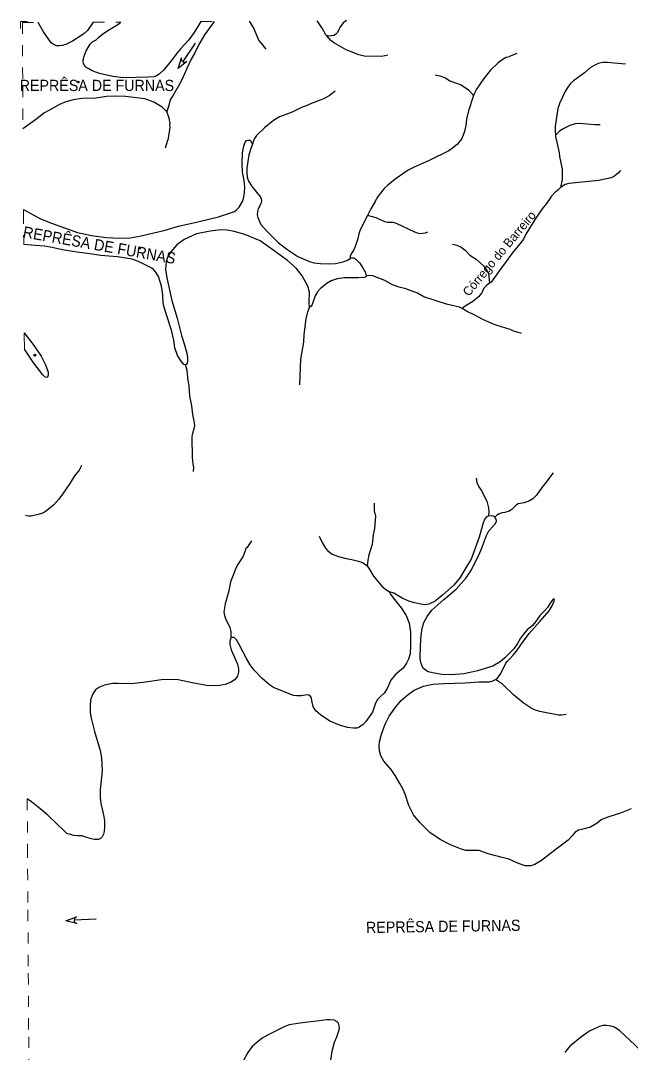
# Model space of a CAD drawing. Extents: x 396 to 422.2, y 7649.8 to 7677.6.
# Drawn here: x 396.05 to 401.48, y 7668.32 to 7677.52 of the extents above; entities that cross this region are included whole.
import ezdxf
from ezdxf.enums import TextEntityAlignment as Align

# ---------------------------------------------------------------- set-up
doc = ezdxf.new("R2010")
doc.units = 0
doc.header["$LTSCALE"] = 0.032
doc.header["$PDMODE"] = 32
doc.header["$PDSIZE"] = 0.016
doc.linetypes.add('SHORT_DASHED', pattern=[2.7, 1.5, -1.2])
for name, color, linetype, lineweight in [('10', 7, 'Continuous', 25), ('2', 7, 'Continuous', 25), ('62', 7, 'SHORT_DASHED', 13), ('63', 7, 'Continuous', 13), ('7', 7, 'Continuous', 25)]:
    doc.layers.add(name, color=color, linetype=linetype, lineweight=lineweight)
doc.layers.add('61', color=7, linetype='Continuous')

msp = doc.modelspace()

# ---------------------------------------------------------------- linework, layer by layer
at = {"layer": '10'}
for p, q in [((397.6028, 7677.3153), (397.4928, 7677.1503)), ((396.7224, 7669.5094), (396.5244, 7669.4992))]:
    msp.add_line(p, q, dxfattribs=at)
for points in [[(397.4808, 7677.1848), (397.4796, 7677.1763), (397.4798, 7677.1704), (397.4829, 7677.1614), (397.4899, 7677.1524), (397.4928, 7677.1503), (397.5004, 7677.1467), (397.5078, 7677.1454), (397.5153, 7677.1454), (397.5223, 7677.1478), (397.5297, 7677.1523), (397.4513, 7677.0881)], [(396.5448, 7669.5294), (396.5373, 7669.5253), (396.5327, 7669.5217), (396.5273, 7669.5138), (396.5243, 7669.5028), (396.5244, 7669.4992), (396.526, 7669.491), (396.5293, 7669.4843), (396.5337, 7669.4783), (396.5399, 7669.4741), (396.5479, 7669.4708), (396.4497, 7669.4954)]]:
    msp.add_lwpolyline(points, close=True, dxfattribs=at)
at = {"layer": '2'}
for points in [[(396.6949, 7677.5016), (396.643, 7677.4274), (396.6152, 7677.4006), (396.5846, 7677.381), (396.5109, 7677.3324), (396.4508, 7677.3034), (396.4174, 7677.2941), (396.3912, 7677.2919), (396.371, 7677.2919), (396.3475, 7677.299), (396.3191, 7677.3182), (396.2508, 7677.4148), (396.2044, 7677.4986)], [(397.6539, 7677.5076), (397.5957, 7677.4088), (397.5477, 7677.3455), (397.4761, 7677.2679), (397.4461, 7677.2329), (397.3789, 7677.1428), (397.3237, 7677.0762), (397.2816, 7677.0379), (397.2581, 7677.0232), (397.2341, 7677.0155), (397.1855, 7677.0106), (397.0746, 7677.009), (396.961, 7677.0057), (396.8697, 7677.0172), (396.7518, 7677.0445), (396.6862, 7677.068), (396.6556, 7677.0849), (396.6294, 7677.1013), (396.6196, 7677.1128), (396.6075, 7677.1324), (396.6043, 7677.145), (396.6043, 7677.1663), (396.6135, 7677.198), (396.6332, 7677.246), (396.6676, 7677.3056), (396.6818, 7677.3214), (396.6917, 7677.3302), (396.7212, 7677.3455), (396.7485, 7677.37), (396.7889, 7677.4039), (396.8386, 7677.4356), (396.9134, 7677.4804), (396.9419, 7677.5032)], [(397.7727, 7677.5083), (397.6875, 7677.3883), (397.6334, 7677.2968), (397.6006, 7677.228), (397.5673, 7677.1723), (397.5296, 7677.0893), (397.4865, 7676.9937), (397.4635, 7676.9494), (397.4073, 7676.8527), (397.3849, 7676.8161), (397.363, 7676.7408), (397.3495, 7676.7065)], [(397.3495, 7676.7065), (397.3379, 7676.7151), (397.3089, 7676.7446), (397.2346, 7676.7888), (397.1533, 7676.82), (397.1052, 7676.8249), (396.9812, 7676.8385), (396.9025, 7676.8435), (396.8129, 7676.8385), (396.7173, 7676.8254), (396.5966, 7676.8205), (396.5169, 7676.8112), (396.4502, 7676.7932), (396.3929, 7676.7675), (396.3, 7676.7151), (396.2541, 7676.6905), (396.1918, 7676.6397), (396.0688, 7676.5507)], [(396.0733, 7675.8334), (396.2252, 7675.7485), (396.3234, 7675.7096), (396.5536, 7675.6277), (396.6805, 7675.6001), (396.8104, 7675.5827), (396.9281, 7675.5776), (397.0243, 7675.5796), (397.1215, 7675.597), (397.3374, 7675.6482), (397.455, 7675.684), (397.6259, 7675.7239), (397.8121, 7675.7679), (397.9185, 7675.8027), (397.9533, 7675.816), (397.9728, 7675.8303), (397.9963, 7675.8528), (398.026, 7675.905), (398.0372, 7675.9439), (398.0434, 7675.9848), (398.0464, 7676.0319), (398.0393, 7676.0923), (398.026, 7676.1659), (398.0208, 7676.2386), (398.026, 7676.3378), (398.0362, 7676.3961), (398.0485, 7676.434), (398.0597, 7676.4463), (398.072, 7676.4504), (398.0894, 7676.4493), (398.0996, 7676.4412), (398.1129, 7676.4162)], [(398.1129, 7676.4162), (398.1037, 7676.3839), (398.0812, 7676.3204), (398.0638, 7676.2007), (398.0638, 7676.1588), (398.0669, 7676.1209), (398.0792, 7676.0841), (398.1099, 7676.035), (398.1774, 7675.9531), (398.1917, 7675.9306), (398.1948, 7675.9101), (398.1886, 7675.8825), (398.1651, 7675.8395), (398.158, 7675.816), (398.1559, 7675.7843), (398.161, 7675.7618), (398.1897, 7675.7004), (398.248, 7675.6329), (398.2869, 7675.595), (398.3452, 7675.5357), (398.4301, 7675.4722), (398.5171, 7675.4149), (398.6225, 7675.3699), (398.6614, 7675.3576), (398.7207, 7675.3505), (398.7923, 7675.3484), (398.8547, 7675.3505), (398.9212, 7675.3668), (398.9622, 7675.3812), (398.9861, 7675.3948)], [(398.6234, 7674.9588), (398.6194, 7675.0067), (398.6214, 7675.0957), (398.6071, 7675.1499), (398.557, 7675.241), (398.5038, 7675.3095), (398.425, 7675.3781), (398.2756, 7675.4876), (398.1815, 7675.553), (398.0464, 7675.6103), (397.9523, 7675.638), (397.8899, 7675.6482), (397.8326, 7675.6513), (397.7364, 7675.64), (397.6157, 7675.6155), (397.5062, 7675.5663), (397.4397, 7675.5183), (397.3875, 7675.4558), (397.3599, 7675.4139), (397.3445, 7675.3679), (397.3394, 7675.2993), (397.3496, 7675.2236), (397.3967, 7675.021), (397.4438, 7674.8634), (397.4827, 7674.7089), (397.5093, 7674.626), (397.5318, 7674.5391), (397.5338, 7674.5053), (397.5348, 7674.4818), (397.5307, 7674.4634), (397.5246, 7674.4531), (397.5165, 7674.4491)], [(397.5165, 7674.4491), (397.5021, 7674.4521), (397.4775, 7674.4818), (397.4468, 7674.5309), (397.4223, 7674.5994), (397.4121, 7674.667), (397.3916, 7674.756), (397.3507, 7674.8859), (397.323, 7674.9698), (397.319, 7675.0016), (397.3159, 7675.0711), (397.3046, 7675.1489), (397.276, 7675.2348), (397.2535, 7675.2747), (397.233, 7675.2973), (397.2166, 7675.3106), (397.1808, 7675.3269), (397.145, 7675.3443), (397.0979, 7675.3689), (397.0427, 7675.3893), (396.9097, 7675.4118), (396.7593, 7675.4241), (396.6672, 7675.4384), (396.5495, 7675.4538), (396.4216, 7675.4722), (396.3275, 7675.4927), (396.26, 7675.507), (396.1791, 7675.5131), (396.0752, 7675.5213)], [(398.9861, 7675.3948), (399.001, 7675.4006), (399.0174, 7675.4006), (399.0348, 7675.3904), (399.0676, 7675.3566), (399.0982, 7675.3126), (399.1208, 7675.2727), (399.1249, 7675.2543), (399.1283, 7675.2391)], [(399.1283, 7675.2391), (399.1238, 7675.2307), (399.1115, 7675.2256), (399.0563, 7675.2226), (398.9345, 7675.2226), (398.868, 7675.2134), (398.8159, 7675.196), (398.779, 7675.1765), (398.7207, 7675.1295), (398.6931, 7675.0998), (398.6736, 7675.0629), (398.647, 7674.9852), (398.6368, 7674.9709), (398.6234, 7674.9588)], [(396.0802, 7674.7328), (396.1601, 7674.6291), (396.2301, 7674.5267), (396.2705, 7674.4473), (396.2934, 7674.3827), (396.2934, 7674.3557), (396.288, 7674.3396), (396.2786, 7674.3369), (396.2638, 7674.3423), (396.2449, 7674.3584), (396.1668, 7674.4635), (396.0811, 7674.5887)], [(400.2151, 7673.0991), (400.1996, 7673.0932), (400.1858, 7673.0765), (400.171, 7673.0411), (400.1347, 7672.9142), (400.0619, 7672.7176), (400.0186, 7672.6448), (399.9645, 7672.5543), (399.9085, 7672.4855), (399.8072, 7672.395), (399.7433, 7672.3419), (399.6853, 7672.3164), (399.6528, 7672.3085), (399.6145, 7672.3144), (399.5584, 7672.3292), (399.5083, 7672.3429), (399.4483, 7672.3695), (399.3736, 7672.4127), (399.3364, 7672.426)], [(400.2807, 7671.6443), (400.2969, 7671.6556), (400.3264, 7671.6989), (400.3716, 7671.7893), (400.3834, 7671.8051), (400.406, 7671.8267), (400.4385, 7671.8601), (400.4631, 7671.8945), (400.5299, 7671.985), (400.5811, 7672.0538), (400.6755, 7672.162), (400.7571, 7672.2564), (400.7856, 7672.2997), (400.8053, 7672.3518), (400.8033, 7672.3616), (400.7935, 7672.3606), (400.7728, 7672.3351), (400.7443, 7672.2859), (400.7158, 7672.2564), (400.6774, 7672.2171), (400.6352, 7672.1571), (400.6086, 7672.1256), (400.5624, 7672.0863), (400.529, 7672.0499), (400.5044, 7672.0125), (400.4768, 7671.9644), (400.4444, 7671.9181), (400.3972, 7671.8709), (400.3628, 7671.8375), (400.3205, 7671.8021), (400.2556, 7671.7647), (400.1189, 7671.7215), (399.9999, 7671.6959), (399.8839, 7671.6871), (399.8043, 7671.688), (399.7197, 7671.7028), (399.6814, 7671.7126), (399.6558, 7671.7264), (399.6322, 7671.75), (399.6145, 7671.7962), (399.6076, 7671.8326), (399.6106, 7671.9467), (399.6184, 7672.0381), (399.6273, 7672.0991), (399.641, 7672.1522), (399.6705, 7672.2062), (399.7128, 7672.2613), (399.819, 7672.3567), (399.9282, 7672.4501), (400.0196, 7672.5494), (400.0668, 7672.6222), (400.0924, 7672.6782), (400.1327, 7672.7539), (400.1563, 7672.808), (400.173, 7672.8552), (400.1986, 7672.927), (400.2212, 7672.9693), (400.2536, 7673.0057), (400.2802, 7673.0342), (400.289, 7673.0558), (400.2871, 7673.0745), (400.2735, 7673.0908)], [(400.2735, 7673.0908), (400.2595, 7673.0991), (400.2408, 7673.102), (400.2151, 7673.0991)], [(399.3364, 7672.426), (399.3382, 7672.4177), (399.3431, 7672.4059), (399.3687, 7672.3714), (399.4404, 7672.2839), (399.4837, 7672.2151), (399.5093, 7672.1463), (399.523, 7672.0656), (399.523, 7671.9467), (399.5191, 7671.8719), (399.5053, 7671.8267), (399.4857, 7671.7893), (399.4581, 7671.747), (399.4247, 7671.7185), (399.3844, 7671.6871), (399.347, 7671.6389), (399.3156, 7671.5651), (399.289, 7671.5238), (399.2595, 7671.4973), (399.2251, 7671.4629), (399.2074, 7671.4255), (399.1848, 7671.3547), (399.1258, 7671.2711), (399.0963, 7671.2397), (399.0688, 7671.2229), (399.0619, 7671.217), (399.0432, 7671.2102), (399.0117, 7671.2102), (398.9616, 7671.218), (398.8888, 7671.2367), (398.8043, 7671.2731), (398.7217, 7671.3291), (398.6794, 7671.3665), (398.6627, 7671.3901), (398.6558, 7671.4039), (398.6469, 7671.4432), (398.641, 7671.4757), (398.6351, 7671.4904), (398.6155, 7671.5061), (398.6017, 7671.5081), (398.5486, 7671.4983), (398.5083, 7671.4983), (398.4807, 7671.5022), (398.3814, 7671.5406), (398.3018, 7671.572), (398.2644, 7671.5966), (398.1976, 7671.6576), (398.1277, 7671.7284), (398.0923, 7671.7746), (398.0609, 7671.8316), (397.996, 7671.9565), (397.9714, 7671.9978), (397.9517, 7672.0175), (397.937, 7672.0194), (397.922, 7672.0178)], [(397.922, 7672.0178), (397.9193, 7672.0037), (397.9124, 7671.987), (397.9124, 7671.9565), (397.9252, 7671.9103), (397.9793, 7671.7824), (397.9881, 7671.7392), (397.9881, 7671.7087), (397.9793, 7671.6743), (397.9743, 7671.6644), (397.9547, 7671.6428), (397.9252, 7671.6202), (397.8711, 7671.6015), (397.819, 7671.5907), (397.7688, 7671.5887), (397.7049, 7671.5907), (397.5761, 7671.6153), (397.4512, 7671.6408), (397.3765, 7671.6448), (397.3047, 7671.6418), (397.1395, 7671.6192), (397.0333, 7671.6064), (396.9173, 7671.6084), (396.8662, 7671.6084), (396.7954, 7671.5927), (396.7501, 7671.575), (396.7157, 7671.5533), (396.6902, 7671.517), (396.6715, 7671.4629), (396.6666, 7671.4058), (396.6666, 7671.3498), (396.6754, 7671.2996), (396.7049, 7671.1807), (396.758, 7671.0125), (396.7688, 7670.9476), (396.7737, 7670.8306), (396.757, 7670.6615), (396.758, 7670.5887), (396.7629, 7670.5396), (396.7875, 7670.4393), (396.7944, 7670.3862), (396.7964, 7670.3301), (396.792, 7670.2907), (396.7855, 7670.2657), (396.7746, 7670.2429), (396.7562, 7670.2255), (396.7377, 7670.2201), (396.7073, 7670.219), (396.6791, 7670.2245), (396.6368, 7670.2364), (396.5923, 7670.2516), (396.5553, 7670.2516), (396.5217, 7670.2549), (396.4609, 7670.2733), (396.4283, 7670.3037), (396.3773, 7670.3536), (396.2915, 7670.4351), (396.2199, 7670.4948), (396.1439, 7670.5556), (396.1063, 7670.5799)], [(400.6302, 7669.9968), (400.5939, 7669.984), (400.5447, 7669.984), (400.4857, 7670.0037), (400.3992, 7670.043), (400.3392, 7670.0587), (400.2143, 7670.0902), (400.1356, 7670.1217), (400.0698, 7670.1197), (400.0157, 7670.1217), (399.9685, 7670.1344), (399.878, 7670.1718), (399.7856, 7670.219), (399.6941, 7670.2819), (399.6056, 7670.3694), (399.5506, 7670.4393), (399.5063, 7670.5209), (399.4739, 7670.6222), (399.4572, 7670.6654), (399.4286, 7670.7175), (399.3854, 7670.7893), (399.349, 7670.8424), (399.2851, 7670.9162), (399.2585, 7670.9643), (399.2477, 7671.0096), (399.2438, 7671.0528), (399.2467, 7671.0902), (399.2654, 7671.1571), (399.2959, 7671.2465), (399.3323, 7671.3183), (399.3923, 7671.4019), (399.4395, 7671.456), (399.5014, 7671.512), (399.5565, 7671.5494), (399.6371, 7671.5848), (399.6932, 7671.5976), (399.7217, 7671.6025), (399.819, 7671.6094), (400.0088, 7671.6143), (400.1307, 7671.6241), (400.2261, 7671.6241), (400.2566, 7671.632), (400.2807, 7671.6443)], [(401.4906, 7670.4933), (401.3844, 7670.4491), (401.29, 7670.4196), (401.2497, 7670.4058), (401.2222, 7670.394), (401.1848, 7670.3655), (401.1258, 7670.3291), (401.058, 7670.3104), (401.0186, 7670.3006), (400.9891, 7670.2829)], [(400.9891, 7670.2829), (400.9626, 7670.2515), (400.9292, 7670.2141), (400.821, 7670.1315), (400.6892, 7670.0322), (400.6302, 7669.9968)], [(398.813, 7668.2512), (398.8233, 7668.3327), (398.8458, 7668.4142), (398.8645, 7668.4611), (398.8814, 7668.5042), (398.8898, 7668.5379), (398.8879, 7668.5576), (398.8795, 7668.582), (398.8692, 7668.5951), (398.8411, 7668.6082), (398.8064, 7668.612), (398.7773, 7668.611), (398.6864, 7668.5998), (398.6049, 7668.5914), (398.5178, 7668.5792), (398.4419, 7668.567), (398.4025, 7668.5529), (398.3491, 7668.5258), (398.2966, 7668.4995), (398.2479, 7668.4752), (398.201, 7668.448), (398.1542, 7668.4114), (398.112, 7668.373), (398.0726, 7668.3224), (398.0342, 7668.2503)], [(401.6352, 7668.276), (401.5241, 7668.3871), (401.3893, 7668.514), (401.3421, 7668.5454), (401.3087, 7668.5553), (401.2684, 7668.5621), (401.2359, 7668.5612), (401.1976, 7668.5503)], [(400.9006, 7668.3212), (400.9557, 7668.3881), (401.0354, 7668.454), (401.1111, 7668.512), (401.1976, 7668.5503)]]:
    msp.add_lwpolyline(points, dxfattribs=at)
for p in [(396.562, 7676.9684), (397.1068, 7675.487), (396.1747, 7674.5346)]:
    msp.add_point(p, dxfattribs=at)
at = {"layer": '62'}
for p, q in [((396.0629, 7677.4977), (396.2044, 7677.4986)), ((396.6949, 7677.5016), (396.9419, 7677.5032)), ((397.6539, 7677.5076), (397.7727, 7677.5083))]:
    msp.add_line(p, q, dxfattribs=at)
for points in [[(396.0629, 7677.4977), (396.0664, 7676.933), (396.0688, 7676.5507)], [(396.0733, 7675.8334), (396.0735, 7675.8035), (396.0749, 7675.5725), (396.0752, 7675.5213)], [(396.0802, 7674.7328), (396.0806, 7674.674), (396.0808, 7674.6358), (396.0811, 7674.5887)], [(396.1063, 7670.5799), (396.1089, 7670.1562), (396.1124, 7669.5914), (396.116, 7669.0267), (396.1195, 7668.462), (396.1231, 7667.8972), (396.1244, 7667.6842)]]:
    msp.add_lwpolyline(points, dxfattribs=at)
at = {"layer": '63'}
msp.add_lwpolyline([(396.1093, 7677.5074), (396.0477, 7677.5074), (396.0477, 7677.4467)], dxfattribs=at)
at = {"layer": '7'}
for points in [[(398.2361, 7677.2621), (398.1915, 7677.3189), (398.1713, 7677.3404), (398.1229, 7677.4535), (398.0875, 7677.5102)], [(398.7745, 7677.3838), (398.7692, 7677.3899), (398.7363, 7677.448), (398.731, 7677.4512), (398.6993, 7677.5026), (398.6906, 7677.514)], [(398.9509, 7677.5155), (398.922, 7677.495), (398.8972, 7677.4618), (398.8689, 7677.4075), (398.8551, 7677.3933), (398.8386, 7677.3824), (398.7927, 7677.3784), (398.7745, 7677.3838)], [(399.3207, 7677.2074), (399.2677, 7677.1953), (399.1106, 7677.1998), (399.0628, 7677.2112), (398.9506, 7677.2546), (398.845, 7677.3161), (398.8126, 7677.3399), (398.7745, 7677.3838)], [(400.4694, 7677.2223), (400.4053, 7677.1973), (400.4023, 7677.1938), (400.3759, 7677.1861), (400.3398, 7677.1656), (400.3044, 7677.1407), (400.2354, 7677.0748), (400.1758, 7676.9994), (400.1114, 7676.9055), (400.0908, 7676.8627), (400.0828, 7676.8489)], [(401.4399, 7677.1289), (401.3384, 7677.1359), (401.2774, 7677.1432), (401.2372, 7677.1423), (401.1942, 7677.1326), (401.165, 7677.1189), (401.1234, 7677.0941), (401.0722, 7677.0504), (400.9762, 7676.979), (400.9499, 7676.9544), (400.9245, 7676.9215), (400.9046, 7676.8886), (400.8506, 7676.776), (400.8497, 7676.7735), (400.835, 7676.7336), (400.8132, 7676.5753), (400.8125, 7676.5318), (400.8155, 7676.4946)], [(399.7418, 7677.0322), (399.7508, 7677.0303), (399.7832, 7677.0234), (399.8336, 7677.0044), (399.8725, 7676.9787), (399.9743, 7676.9429), (400.0384, 7676.8981), (400.0828, 7676.8489)], [(398.8502, 7676.8865), (398.7982, 7676.8444), (398.7464, 7676.8179), (398.7175, 7676.8068), (398.631, 7676.7737), (398.6087, 7676.7626), (398.5497, 7676.7418), (398.4683, 7676.7004), (398.3561, 7676.6577), (398.3025, 7676.6267), (398.2204, 7676.5591), (398.151, 7676.4913), (398.1317, 7676.4643), (398.124, 7676.4433), (398.1129, 7676.4162)], [(400.0828, 7676.8489), (400.0382, 7676.7129), (400.0219, 7676.6364), (400.0158, 7676.5821), (400.0032, 7676.5265), (399.9925, 7676.4941), (399.9761, 7676.4592), (399.939, 7676.4132), (399.898, 7676.3785), (399.8642, 7676.3568), (399.6898, 7676.2679), (399.5567, 7676.211), (399.5012, 7676.1825), (399.3863, 7676.1025), (399.3193, 7676.05), (399.288, 7676.0205), (399.2231, 7675.9372), (399.2212, 7675.9268), (399.2138, 7675.9177), (399.209, 7675.9028), (399.1696, 7675.84), (399.1379, 7675.7777)], [(397.3376, 7676.3825), (397.3587, 7676.4503), (397.3618, 7676.4518), (397.3759, 7676.5251), (397.3792, 7676.5676), (397.3769, 7676.583), (397.3792, 7676.598), (397.372, 7676.6459), (397.3495, 7676.7065)], [(401.2144, 7676.5883), (401.1802, 7676.5866), (401.1698, 7676.5875), (401.0266, 7676.6), (400.9916, 7676.5952), (400.9421, 7676.5806), (400.9119, 7676.5656), (400.8901, 7676.5547), (400.8505, 7676.5298), (400.8155, 7676.4946)], [(400.8155, 7676.4946), (400.818, 7676.4627), (400.8213, 7676.4605), (400.8476, 7676.3369), (400.8499, 7676.3041), (400.8756, 7676.1907), (400.8755, 7676.1007), (400.8593, 7676.0286)], [(401.3932, 7676.1807), (401.3744, 7676.1565), (401.3325, 7676.1228), (401.3, 7676.1108), (401.2408, 7676.0993), (401.2, 7676.0913), (400.9345, 7676.0641), (400.9023, 7676.0544), (400.8593, 7676.0286)], [(400.8593, 7676.0286), (400.8359, 7676.0058), (400.8307, 7676.0048), (400.8254, 7675.9974), (400.8167, 7675.9924), (400.7739, 7675.9441), (400.7738, 7675.9439), (400.7353, 7675.8866), (400.697, 7675.8371), (400.6462, 7675.7628), (400.6427, 7675.7616), (400.5513, 7675.6142), (400.5285, 7675.5692), (400.4855, 7675.5106), (400.4294, 7675.4427), (400.3604, 7675.347), (400.33, 7675.3105), (400.2421, 7675.1855), (400.2262, 7675.1753)], [(399.1379, 7675.7777), (399.0738, 7675.6516), (399.0612, 7675.6155), (399.0492, 7675.5625), (399.0331, 7675.5111), (399.0199, 7675.4798), (399.0089, 7675.4614), (398.9912, 7675.4318), (398.9861, 7675.4164), (398.9861, 7675.3948)], [(399.6752, 7675.6316), (399.6521, 7675.6206), (399.6054, 7675.6168), (399.5928, 7675.6184), (399.5599, 7675.6301), (399.398, 7675.7075), (399.3686, 7675.7158), (399.3337, 7675.7168), (399.318, 7675.7173), (399.2929, 7675.7221), (399.2162, 7675.7569), (399.1379, 7675.7777)], [(399.8974, 7675.5236), (399.9367, 7675.5152), (399.9749, 7675.4967), (400.0108, 7675.4693), (400.0527, 7675.4259), (400.1078, 7675.3894), (400.1711, 7675.3331), (400.1763, 7675.3269), (400.1972, 7675.3024), (400.218, 7675.2633), (400.2262, 7675.1753)], [(399.9834, 7674.9491), (399.9596, 7674.9628), (399.8444, 7674.99), (399.6416, 7675.0534), (399.584, 7675.0873), (399.4803, 7675.1266), (399.4201, 7675.1408), (399.3611, 7675.1621), (399.2923, 7675.1993), (399.1855, 7675.2401), (399.1852, 7675.2402), (399.1529, 7675.2458), (399.1283, 7675.2391)], [(400.2262, 7675.1753), (400.2038, 7675.1575), (400.1755, 7675.131), (400.1571, 7675.0906), (400.128, 7675.0558), (400.0783, 7675.0134), (400.0088, 7674.9698), (399.9834, 7674.9491)], [(398.5369, 7674.2716), (398.5438, 7674.4983), (398.5723, 7674.6498), (398.5758, 7674.7174), (398.5936, 7674.8571), (398.6088, 7674.9199), (398.6234, 7674.9588)], [(400.5112, 7674.7279), (400.4342, 7674.7505), (400.4116, 7674.7625), (400.2952, 7674.7986), (400.2538, 7674.8141), (400.166, 7674.8534), (400.0958, 7674.8917), (400.0288, 7674.9228), (399.9834, 7674.9491)], [(397.5873, 7673.4987), (397.5907, 7673.5358), (397.5851, 7673.562), (397.5788, 7673.622), (397.5771, 7673.8052), (397.5803, 7673.8291), (397.5992, 7673.9046), (397.5985, 7673.9312), (397.5835, 7674.007), (397.5737, 7674.0846), (397.5548, 7674.1729), (397.5507, 7674.2629), (397.5388, 7674.326), (397.5366, 7674.3463), (397.5352, 7674.3597), (397.5307, 7674.4014), (397.5165, 7674.4491)], [(396.5912, 7673.5504), (396.5682, 7673.5108), (396.5285, 7673.4598), (396.4872, 7673.3923), (396.4214, 7673.296), (396.3868, 7673.2503), (396.3407, 7673.1969), (396.2692, 7673.1405), (396.2518, 7673.1307), (396.217, 7673.118), (396.1406, 7673.0999), (396.1169, 7673.1007), (396.0904, 7673.1059)], [(400.1088, 7673.4375), (400.1134, 7673.3998), (400.1321, 7673.3617), (400.1523, 7673.3324), (400.2023, 7673.2325), (400.2183, 7673.1752), (400.2215, 7673.1305), (400.2151, 7673.0991)], [(400.7932, 7673.4862), (400.7204, 7673.3883), (400.6922, 7673.3561), (400.6451, 7673.2859), (400.6129, 7673.2559), (400.5823, 7673.2356), (400.5362, 7673.2176), (400.4815, 7673.209), (400.4677, 7673.2011), (400.426, 7673.1599), (400.4033, 7673.1445), (400.3639, 7673.1334), (400.3386, 7673.1303), (400.3131, 7673.1208), (400.2886, 7673.1063), (400.2735, 7673.0908)], [(399.1986, 7673.2144), (399.1986, 7673.1465), (399.2039, 7673.1205), (399.2071, 7673.1183), (399.2094, 7673.099), (399.2007, 7672.9913), (399.1911, 7672.9336), (399.1815, 7672.8471), (399.151, 7672.754), (399.1418, 7672.7077), (399.1361, 7672.6572)], [(398.1049, 7672.8812), (398.0631, 7672.8183), (398.0591, 7672.8176), (398.0525, 7672.8074), (398.0498, 7672.7915), (398.03, 7672.7442), (397.9825, 7672.6683), (397.963, 7672.6293), (397.955, 7672.6039), (397.9176, 7672.5148), (397.904, 7672.4347), (397.871, 7672.3181), (397.8602, 7672.2488), (397.8639, 7672.2142), (397.8759, 7672.1783), (397.8964, 7672.1407), (397.9136, 7672.109), (397.9223, 7672.0714), (397.922, 7672.0178)], [(398.7084, 7672.9209), (398.7388, 7672.8593), (398.7657, 7672.8154), (398.7853, 7672.7918), (398.8257, 7672.761), (398.8803, 7672.7397), (398.9505, 7672.7223), (399.001, 7672.7147), (399.0579, 7672.7), (399.1001, 7672.6835), (399.1361, 7672.6572)], [(399.1361, 7672.6572), (399.1547, 7672.6312), (399.1933, 7672.565), (399.2675, 7672.4749), (399.2851, 7672.4605), (399.3102, 7672.4399), (399.3364, 7672.426)], [(400.9112, 7671.3336), (400.8672, 7671.3254), (400.8408, 7671.3256), (400.6761, 7671.358), (400.6366, 7671.3706), (400.5989, 7671.3895), (400.5437, 7671.4262), (400.5262, 7671.4379), (400.4394, 7671.5072), (400.3411, 7671.6035), (400.2807, 7671.6443)]]:
    msp.add_lwpolyline(points, dxfattribs=at)

# ---------------------------------------------------------------- texts
at = {"layer": '61', "width": 0.95}
msp.add_text('REPRÊSA DE FURNAS', height=0.1, dxfattribs=at).set_placement((396.7276, 7676.8883), align=Align.CENTER)
at = {"layer": '61'}
msp.add_text('Córrego do Barreiro', height=0.08, rotation=50.191, dxfattribs=at).set_placement((400.3444, 7675.4152), align=Align.CENTER)
at = {"layer": '61', "width": 0.95}
for rotation, p in [(349.992, (396.7408, 7675.466)), (0.839, (399.815, 7669.3951))]:
    msp.add_text('REPRÊSA DE FURNAS', height=0.1, rotation=rotation, dxfattribs=at).set_placement(p, align=Align.CENTER)

doc.saveas('drawing.dxf')
